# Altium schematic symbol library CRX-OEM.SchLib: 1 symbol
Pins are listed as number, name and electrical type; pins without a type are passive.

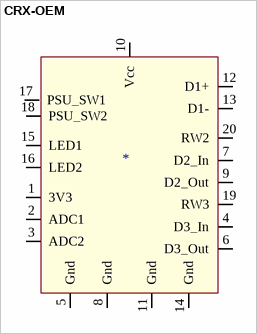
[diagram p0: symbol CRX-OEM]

## CRX-OEM
designator *
CRX OEM module
footprint CRX_OEM-SMD (CRX OEM Version SMD connection)
footprint CRX_OEM-THRU (Footprint not found)
pins: 1 3V3 (power), 2 ADC1, 3 ADC2, 4 D3_In, 5 Gnd, 6 D3_Out, 7 D2_In, 8 Gnd, 9 D2_Out, 10 Vcc, 11 Gnd, 12 D1+, 13 D1-, 14 Gnd, 15 LED1, 16 LED2, 17 PSU_SW1, 18 PSU_SW2, 19 RW3, 20 RW2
